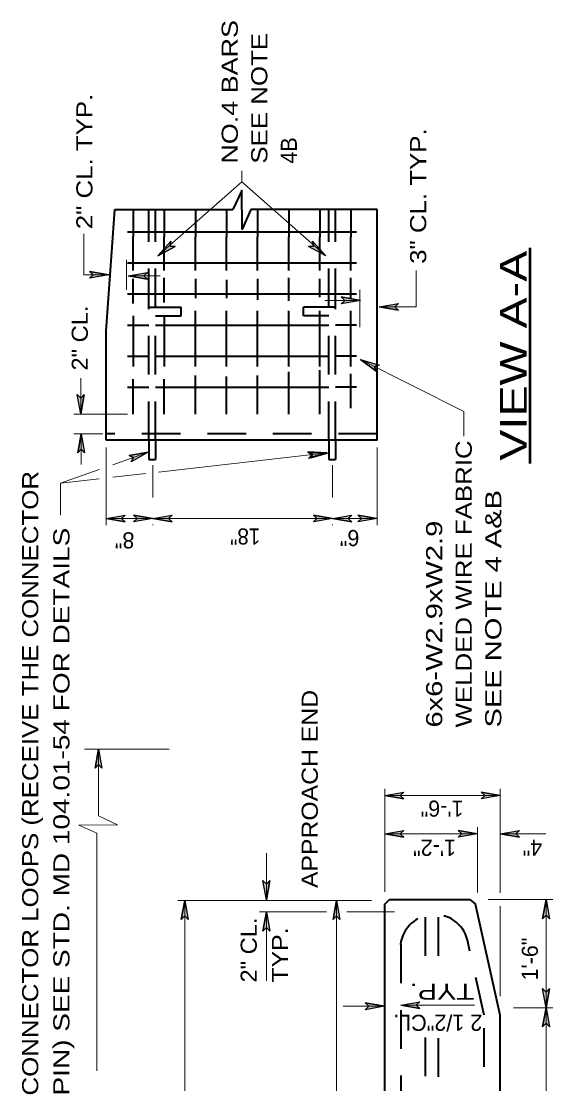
# Model space of a CAD drawing. Extents: x 12.6 to 19.5, y 6.1 to 16.3.
# Drawn here: x 12.689 to 14.668, y 12.348 to 16.307 of the extents above; entities that cross this region are included whole.
import ezdxf
from ezdxf.enums import TextEntityAlignment as Align

# ---------------------------------------------------------------- set-up
doc = ezdxf.new("R2010")
doc.units = 0
doc.header["$LTSCALE"] = 0.024
doc.linetypes.add('DOT_DASHED', pattern=[7.7, 5, -1.2, 0.3, -1.2])
doc.linetypes.add('LONG_DASHED', pattern=[7.5, 6, -1.5])
for name, color, linetype, lineweight in [('1', 7, 'Continuous', 35), ('10', 7, 'Continuous', 25), ('12', 7, 'Continuous', 53)]:
    doc.layers.add(name, color=color, linetype=linetype, lineweight=lineweight)

msp = doc.modelspace()

# ---------------------------------------------------------------- hatches: boundary and pattern name
at = {"layer": '10'}
for points in [[(13.2621, 15.4673), (13.1979, 15.4333), (13.2466, 15.4872), (13.2437, 15.4689)], [(13.7742, 15.4873), (13.8229, 15.4334), (13.7587, 15.4674), (13.7771, 15.469)], [(12.9436, 15.3746), (13.0151, 15.362), (12.9436, 15.3494), (12.9571, 15.362)], [(13.1589, 15.3461), (13.0874, 15.3587), (13.1589, 15.3713), (13.1454, 15.3587)], [(13.8805, 15.2797), (13.952, 15.2671), (13.8805, 15.2545), (13.894, 15.2671)], [(14.0935, 15.2305), (14.022, 15.2431), (14.0935, 15.2557), (14.08, 15.2431)], [(14.0104, 15.0033), (13.9522, 15.0466), (14.0217, 15.0258), (14.004, 15.0206)], [(12.9233, 14.9162), (12.9107, 14.8447), (12.8981, 14.9162), (12.9107, 14.9027)], [(12.8995, 14.6985), (12.9121, 14.77), (12.9247, 14.6985), (12.9121, 14.712)], [(13.0908, 14.689), (13.1624, 14.7008), (13.0991, 14.6652), (13.1077, 14.6816)], [(13.7563, 14.7029), (13.8288, 14.6984), (13.7592, 14.6778), (13.7712, 14.6919)], [(13.0765, 14.4418), (13.005, 14.4544), (13.0765, 14.467), (13.063, 14.4544)], [(13.1079, 14.467), (13.1794, 14.4544), (13.1079, 14.4418), (13.1214, 14.4544)], [(13.2509, 14.4418), (13.1794, 14.4544), (13.2509, 14.467), (13.2374, 14.4544)], [(13.777, 14.467), (13.8485, 14.4544), (13.777, 14.4418), (13.7905, 14.4544)], [(13.92, 14.4418), (13.8485, 14.4544), (13.92, 14.467), (13.9065, 14.4544)], [(13.9427, 14.467), (14.0142, 14.4544), (13.9427, 14.4418), (13.9562, 14.4544)], [(12.9644, 13.5238), (12.977, 13.5953), (12.9896, 13.5238), (12.977, 13.5373)], [(14.114, 13.4098), (14.0425, 13.4224), (14.114, 13.435), (14.1005, 13.4224)], [(14.4013, 13.435), (14.4728, 13.4224), (14.4013, 13.4098), (14.4148, 13.4224)], [(14.114, 13.2666), (14.0425, 13.2792), (14.114, 13.2918), (14.1005, 13.2792)], [(14.3161, 13.2918), (14.3876, 13.2792), (14.3161, 13.2666), (14.3296, 13.2792)], [(14.5443, 13.2664), (14.4728, 13.279), (14.5443, 13.2916), (14.5308, 13.279)], [(13.6145, 13.1051), (13.6019, 13.0336), (13.5893, 13.1051), (13.6019, 13.0916)], [(13.2852, 12.9596), (13.2978, 13.0311), (13.3104, 12.9596), (13.2978, 12.9731)], [(13.8509, 12.9596), (13.8635, 13.0311), (13.8761, 12.9596), (13.8635, 12.9731)], [(14.6306, 12.9627), (14.6432, 13.0342), (14.6558, 12.9627), (14.6432, 12.9762)], [(13.5893, 12.9169), (13.6019, 12.9884), (13.6145, 12.9169), (13.6019, 12.9304)], [(14.6558, 12.7028), (14.6432, 12.6313), (14.6306, 12.7028), (14.6432, 12.6893)], [(13.9699, 12.6492), (14.0414, 12.6366), (13.9699, 12.624), (13.9834, 12.6366)], [(14.1736, 12.6282), (14.1021, 12.6408), (14.1736, 12.6534), (14.1601, 12.6408)], [(14.6306, 12.5598), (14.6432, 12.6313), (14.6558, 12.5598), (14.6432, 12.5733)]]:
    msp.add_hatch(color=256, dxfattribs=at).paths.add_polyline_path(points)

# ---------------------------------------------------------------- linework, layer by layer
at = {"layer": '1'}
for p, q in [((13.0052, 15.1519), (13.0384, 15.6061)), ((13.0384, 15.6061), (13.4771, 15.6061)), ((13.1061, 15.6061), (13.1061, 15.5035)), ((13.2219, 15.6061), (13.2219, 15.5035)), ((13.3378, 15.6061), (13.3378, 15.5035)), ((13.4536, 15.6061), (13.4536, 15.5035)), ((14.0143, 15.6061), (13.5437, 15.6061)), ((13.5694, 15.6061), (13.5694, 15.5035)), ((13.6852, 15.6061), (13.6852, 15.5035)), ((13.8011, 15.6061), (13.8011, 15.5035)), ((13.9169, 15.6061), (13.9169, 15.5035)), ((14.0143, 14.7465), (14.0143, 15.6061)), ((13.0844, 15.5224), (13.9376, 15.5224)), ((13.1061, 15.3778), (13.1061, 15.5035)), ((13.2219, 15.3778), (13.2219, 15.5035)), ((13.3378, 15.3778), (13.3378, 15.5035)), ((13.4536, 15.3778), (13.4536, 15.5035)), ((13.5694, 15.3778), (13.5694, 15.5035)), ((13.6852, 15.3778), (13.6852, 15.5035)), ((13.8011, 15.3778), (13.8011, 15.5035)), ((13.9169, 15.3778), (13.9169, 15.5035)), ((13.0844, 15.4066), (13.9376, 15.4066)), ((13.1061, 15.2554), (13.1061, 15.3472)), ((13.2219, 15.2588), (13.2219, 15.3506)), ((13.3378, 15.3472), (13.3378, 15.2758)), ((13.4536, 15.3438), (13.4536, 15.2758)), ((13.5694, 15.3472), (13.5694, 15.2692)), ((13.6852, 15.2656), (13.6852, 15.3506)), ((13.8011, 15.2792), (13.8011, 15.3472)), ((13.9169, 15.2725), (13.9169, 15.3506)), ((13.0844, 15.2908), (13.9376, 15.2908)), ((13.1061, 15.2097), (13.1061, 15.021)), ((13.2219, 15.2097), (13.2219, 15.021)), ((13.0844, 15.175), (13.1643, 15.175)), ((13.1898, 15.175), (13.8342, 15.175)), ((13.9376, 15.175), (13.8597, 15.175)), ((13.0052, 14.7465), (13.0052, 15.1519)), ((13.0844, 15.0592), (13.1643, 15.0592)), ((13.1898, 15.0592), (13.8342, 15.0592)), ((13.9376, 15.0592), (13.8597, 15.0592)), ((13.8011, 14.8431), (13.8011, 15.0074)), ((13.1061, 14.8431), (13.1061, 14.9731)), ((13.2219, 14.8431), (13.2219, 14.9735)), ((13.3378, 14.8431), (13.3378, 14.9871)), ((13.4536, 14.8431), (13.4536, 14.9836)), ((13.5694, 14.8431), (13.5694, 14.9871)), ((13.6852, 14.8431), (13.6852, 15.0006)), ((13.9169, 14.8648), (13.9169, 14.9938)), ((13.0844, 14.9433), (13.1643, 14.9433)), ((13.1898, 14.9433), (13.8342, 14.9433)), ((13.9376, 14.9433), (13.8597, 14.9433)), ((14.0143, 14.7465), (13.0052, 14.7465)), ((13.1643, 14.7465), (13.1643, 14.6736)), ((13.1898, 14.7465), (13.1898, 14.6736)), ((13.8342, 14.7465), (13.8342, 14.6736)), ((13.8597, 14.7465), (13.8597, 14.6736)), ((13.7651, 14.7018), (13.8288, 14.6984)), ((13.7651, 14.7018), (13.7741, 14.6922)), ((13.7674, 14.6809), (13.8288, 14.6984)), ((13.7674, 14.6809), (13.7741, 14.6922)), ((13.1643, 14.6736), (13.1898, 14.6736)), ((13.8342, 14.6736), (13.8597, 14.6736)), ((14.0422, 13.0162), (14.0601, 13.0342)), ((14.0601, 13.0342), (14.3593, 13.0342)), ((14.3593, 13.0342), (14.3811, 13.0167)), ((14.4729, 12.6034), (14.3811, 13.0167))]:
    msp.add_line(p, q, dxfattribs=at)
at = {"layer": '1', "linetype": 'LONG_DASHED'}
for p, q in [((13.1643, 15.2414), (13.1643, 15.6061)), ((13.1898, 15.2414), (13.1898, 15.6061)), ((13.8342, 15.2414), (13.8342, 15.6061)), ((13.8597, 15.2414), (13.8597, 15.6061)), ((13.2843, 15.2097), (13.2843, 15.2414)), ((13.7397, 15.2097), (13.7397, 15.2414)), ((14.0143, 14.7702), (13.0052, 14.7702)), ((14.1928, 12.9684), (14.1928, 12.7394)), ((14.2415, 12.9684), (14.2415, 12.7394)), ((14.1021, 12.8664), (14.1021, 10.4224)), ((14.1928, 12.5199), (14.1928, 12.3566)), ((14.2415, 12.5182), (14.2415, 12.3548))]:
    msp.add_line(p, q, dxfattribs=at)
for points in [[(13.1643, 14.7465), (13.1643, 15.2414), (13.2843, 15.2414)], [(13.1898, 14.7465), (13.1898, 15.2097), (13.2843, 15.2097)], [(13.8597, 14.7465), (13.8597, 15.2414), (13.7397, 15.2414)], [(13.8342, 14.7465), (13.8342, 15.2097), (13.7397, 15.2097)], [(14.4131, 11.1916), (14.4131, 12.6034), (14.3534, 12.8719)]]:
    msp.add_lwpolyline(points, dxfattribs=at)
at = {"layer": '1'}
for points in [[(13.3378, 15.021), (13.3378, 15.1433), (13.3378, 15.2283)], [(13.4536, 15.021), (13.4536, 15.1433), (13.4536, 15.2283)], [(13.5694, 15.021), (13.5694, 15.1433), (13.5694, 15.2283)], [(13.6852, 15.021), (13.6852, 15.1433), (13.6852, 15.2283)], [(13.8011, 15.021), (13.8011, 15.1433), (13.8011, 15.2283)], [(13.9169, 15.021), (13.9169, 15.1433), (13.9169, 15.2283)], [(14.0422, 13.0162), (14.0422, 11.1916), (14.4729, 11.1916), (14.4729, 12.6034)]]:
    msp.add_lwpolyline(points, dxfattribs=at)
at = {"layer": '1', "linetype": 'LONG_DASHED'}
msp.add_arc((14.22776, 12.85181), 0.12725, 9.07504, 173.4317, dxfattribs=at)
at = {"layer": '10', "lineweight": 13}
for p, q in [((13.5104, 15.7092), (13.5104, 15.7503)), ((13.5104, 15.7092), (13.1979, 15.4333)), ((13.5104, 15.7092), (13.8229, 15.4333)), ((13.0808, 15.3058), (13.0808, 15.4182)), ((13.0874, 15.3587), (13.2063, 15.3587)), ((13.9496, 15.1672), (13.9496, 15.3059)), ((13.952, 15.2671), (13.82, 15.2671)), ((12.9107, 14.8447), (12.9107, 14.9767)), ((13.085, 14.8432), (12.8857, 14.8432)), ((12.9935, 14.77), (12.8857, 14.77)), ((12.9121, 14.77), (12.9121, 14.6551)), ((13.005, 14.7184), (13.005, 14.4294)), ((13.1624, 14.7008), (13.03, 14.6543)), ((13.8288, 14.6984), (13.1999, 14.6272)), ((14.0142, 14.4294), (14.0142, 14.7193)), ((12.835, 14.5858), (12.98, 14.6368)), ((13.03, 14.6079), (13.1526, 14.6218)), ((12.835, 14.5858), (12.98, 14.6021)), ((12.835, 14.4662), (12.835, 14.5858)), ((13.24, 13.5953), (12.9251, 13.5953)), ((12.977, 13.5953), (12.977, 13.3457)), ((14.0425, 13.0632), (14.0425, 13.4474)), ((14.4728, 13.4224), (14.0425, 13.4224)), ((14.4728, 13.4474), (14.4728, 13.0592)), ((14.3876, 13.0611), (14.3876, 13.3042)), ((12.9705, 12.3967), (12.9705, 13.2819)), ((14.3876, 13.2792), (14.0425, 13.2792)), ((14.4728, 13.279), (14.6429, 13.279)), ((13.6019, 13.0311), (13.6019, 13.2075)), ((13.5795, 13.0311), (13.2728, 13.0311)), ((13.2978, 8.7037), (13.2978, 13.0311)), ((13.9935, 13.0311), (13.5795, 13.0311)), ((14.4281, 13.0342), (14.6682, 13.0342)), ((13.5769, 12.9884), (13.8264, 12.9884)), ((13.6019, 12.9884), (13.6019, 12.7319)), ((14.0787, 12.9884), (13.9013, 12.9884)), ((14.4728, 12.6741), (14.4728, 13.0092)), ((14.0422, 12.6366), (13.8885, 12.6366)), ((14.1021, 12.6408), (14.377, 12.6408)), ((14.5218, 12.6313), (14.6682, 12.6313))]:
    msp.add_line(p, q, dxfattribs=at)
at = {"layer": '10'}
for p, q in [((13.1979, 15.4333), (13.2466, 15.4872)), ((13.8229, 15.4334), (13.7742, 15.4873)), ((13.1979, 15.4333), (13.2621, 15.4673)), ((13.8229, 15.4334), (13.7587, 15.4674)), ((13.0151, 15.362), (12.9436, 15.3746)), ((13.0151, 15.362), (12.9436, 15.3494)), ((13.0874, 15.3587), (13.1589, 15.3713)), ((13.0874, 15.3587), (13.1589, 15.3461)), ((13.952, 15.2671), (13.8805, 15.2797)), ((13.952, 15.2671), (13.8805, 15.2545)), ((14.022, 15.2431), (14.0935, 15.2557)), ((14.022, 15.2431), (14.0935, 15.2305)), ((13.9522, 15.0466), (14.0104, 15.0033)), ((13.9522, 15.0466), (14.0217, 15.0258)), ((12.9107, 14.8447), (12.8981, 14.9162)), ((12.9107, 14.8447), (12.9233, 14.9162)), ((12.9121, 14.77), (12.8995, 14.6985)), ((12.9121, 14.77), (12.9247, 14.6985)), ((13.1624, 14.7008), (13.0908, 14.689)), ((13.1624, 14.7008), (13.0991, 14.6652)), ((13.8288, 14.6984), (13.7563, 14.7029)), ((13.8288, 14.6984), (13.7592, 14.6778)), ((13.005, 14.4544), (13.0765, 14.467)), ((13.005, 14.4544), (13.0765, 14.4418)), ((13.1794, 14.4544), (13.1079, 14.467)), ((13.1794, 14.4544), (13.1079, 14.4418)), ((13.1794, 14.4544), (13.2509, 14.467)), ((13.1794, 14.4544), (13.2509, 14.4418)), ((13.8485, 14.4544), (13.777, 14.467)), ((13.8485, 14.4544), (13.777, 14.4418)), ((13.8485, 14.4544), (13.92, 14.467)), ((13.8485, 14.4544), (13.92, 14.4418)), ((14.0142, 14.4544), (13.9427, 14.467)), ((14.0142, 14.4544), (13.9427, 14.4418)), ((12.977, 13.5953), (12.9644, 13.5238)), ((12.977, 13.5953), (12.9896, 13.5238)), ((14.0425, 13.4224), (14.114, 13.435)), ((14.0425, 13.4224), (14.114, 13.4098)), ((14.4728, 13.4224), (14.4013, 13.435)), ((14.4728, 13.4224), (14.4013, 13.4098)), ((14.0425, 13.2792), (14.114, 13.2918)), ((14.0425, 13.2792), (14.114, 13.2666)), ((14.3876, 13.2792), (14.3161, 13.2918)), ((14.3876, 13.2792), (14.3161, 13.2666)), ((14.4728, 13.279), (14.5443, 13.2916)), ((14.4728, 13.279), (14.5443, 13.2664)), ((13.6019, 13.0336), (13.5893, 13.1051)), ((13.6019, 13.0336), (13.6145, 13.1051)), ((13.2978, 13.0311), (13.2852, 12.9596)), ((13.2978, 13.0311), (13.3104, 12.9596)), ((13.8635, 13.0311), (13.8509, 12.9596)), ((13.8635, 13.0311), (13.8761, 12.9596)), ((14.6432, 13.0342), (14.6306, 12.9627)), ((14.6432, 13.0342), (14.6558, 12.9627)), ((13.6019, 12.9884), (13.5893, 12.9169)), ((13.6019, 12.9884), (13.6145, 12.9169)), ((14.6432, 12.6313), (14.6306, 12.7028)), ((14.6432, 12.6313), (14.6558, 12.7028)), ((14.0414, 12.6366), (13.9699, 12.6492)), ((14.0414, 12.6366), (13.9699, 12.624)), ((14.1021, 12.6408), (14.1736, 12.6534)), ((14.1021, 12.6408), (14.1736, 12.6282)), ((14.6432, 12.6313), (14.6306, 12.5598)), ((14.6432, 12.6313), (14.6558, 12.5598))]:
    msp.add_line(p, q, dxfattribs=at)
at = {"layer": '10', "linetype": 'DOT_DASHED', "lineweight": 13}
for p, q in [((13.1794, 14.6524), (13.1794, 14.4294)), ((13.8485, 14.6524), (13.8485, 14.4294))]:
    msp.add_line(p, q, dxfattribs=at)
at = {"layer": '10', "lineweight": 35}
msp.add_lwpolyline([(13.5438, 15.6061), (13.5116, 15.5325), (13.5104, 15.6763), (13.4771, 15.6061)], dxfattribs=at)
at = {"layer": '10', "lineweight": 13}
for points in [[(13.0151, 15.362), (12.9228, 15.362), (12.9228, 15.5149)], [(14.022, 15.2431), (14.1602, 15.2431), (14.1602, 15.3787)], [(13.9522, 15.0466), (14.3378, 14.853), (14.3378, 14.761)], [(13.005, 14.4544), (13.1794, 14.4544), (13.8485, 14.4544), (14.0142, 14.4544)], [(12.9705, 13.2819), (12.9034, 13.3113), (13.0471, 13.3124), (12.977, 13.3457)], [(13.8635, 9.9472), (13.8635, 11.742), (13.8635, 13.0311)], [(14.6432, 11.1945), (14.6432, 12.6313), (14.6432, 13.0342)]]:
    msp.add_lwpolyline(points, dxfattribs=at)
at = {"layer": '10'}
for points in [[(13.2621, 15.4673), (13.1979, 15.4333), (13.2466, 15.4872), (13.2437, 15.4689)], [(13.7742, 15.4873), (13.8229, 15.4334), (13.7587, 15.4674), (13.7771, 15.469)], [(12.9436, 15.3746), (13.0151, 15.362), (12.9436, 15.3494), (12.9571, 15.362)], [(13.1589, 15.3461), (13.0874, 15.3587), (13.1589, 15.3713), (13.1454, 15.3587)], [(13.8805, 15.2797), (13.952, 15.2671), (13.8805, 15.2545), (13.894, 15.2671)], [(14.0935, 15.2305), (14.022, 15.2431), (14.0935, 15.2557), (14.08, 15.2431)], [(14.0104, 15.0033), (13.9522, 15.0466), (14.0217, 15.0258), (14.004, 15.0206)], [(12.9233, 14.9162), (12.9107, 14.8447), (12.8981, 14.9162), (12.9107, 14.9027)], [(12.8995, 14.6985), (12.9121, 14.77), (12.9247, 14.6985), (12.9121, 14.712)], [(13.0908, 14.689), (13.1624, 14.7008), (13.0991, 14.6652), (13.1077, 14.6816)], [(13.7563, 14.7029), (13.8288, 14.6984), (13.7592, 14.6778), (13.7712, 14.6919)], [(13.0765, 14.4418), (13.005, 14.4544), (13.0765, 14.467), (13.063, 14.4544)], [(13.1079, 14.467), (13.1794, 14.4544), (13.1079, 14.4418), (13.1214, 14.4544)], [(13.2509, 14.4418), (13.1794, 14.4544), (13.2509, 14.467), (13.2374, 14.4544)], [(13.777, 14.467), (13.8485, 14.4544), (13.777, 14.4418), (13.7905, 14.4544)], [(13.92, 14.4418), (13.8485, 14.4544), (13.92, 14.467), (13.9065, 14.4544)], [(13.9427, 14.467), (14.0142, 14.4544), (13.9427, 14.4418), (13.9562, 14.4544)], [(12.9644, 13.5238), (12.977, 13.5953), (12.9896, 13.5238), (12.977, 13.5373)], [(14.114, 13.4098), (14.0425, 13.4224), (14.114, 13.435), (14.1005, 13.4224)], [(14.4013, 13.435), (14.4728, 13.4224), (14.4013, 13.4098), (14.4148, 13.4224)], [(14.114, 13.2666), (14.0425, 13.2792), (14.114, 13.2918), (14.1005, 13.2792)], [(14.3161, 13.2918), (14.3876, 13.2792), (14.3161, 13.2666), (14.3296, 13.2792)], [(14.5443, 13.2664), (14.4728, 13.279), (14.5443, 13.2916), (14.5308, 13.279)], [(13.6145, 13.1051), (13.6019, 13.0336), (13.5893, 13.1051), (13.6019, 13.0916)], [(13.2852, 12.9596), (13.2978, 13.0311), (13.3104, 12.9596), (13.2978, 12.9731)], [(13.8509, 12.9596), (13.8635, 13.0311), (13.8761, 12.9596), (13.8635, 12.9731)], [(14.6306, 12.9627), (14.6432, 13.0342), (14.6558, 12.9627), (14.6432, 12.9762)], [(13.5893, 12.9169), (13.6019, 12.9884), (13.6145, 12.9169), (13.6019, 12.9304)], [(14.6558, 12.7028), (14.6432, 12.6313), (14.6306, 12.7028), (14.6432, 12.6893)], [(13.9699, 12.6492), (14.0414, 12.6366), (13.9699, 12.624), (13.9834, 12.6366)], [(14.1736, 12.6282), (14.1021, 12.6408), (14.1736, 12.6534), (14.1601, 12.6408)], [(14.6306, 12.5598), (14.6432, 12.6313), (14.6558, 12.5598), (14.6432, 12.5733)]]:
    msp.add_lwpolyline(points, close=True, dxfattribs=at)
for points in [[(13.2621, 15.4673), (13.2437, 15.4689), (13.2466, 15.4872)], [(13.7742, 15.4873), (13.7771, 15.469), (13.7587, 15.4674)], [(12.9436, 15.3746), (12.9571, 15.362), (12.9436, 15.3494)], [(13.1589, 15.3461), (13.1454, 15.3587), (13.1589, 15.3713)], [(13.8805, 15.2797), (13.894, 15.2671), (13.8805, 15.2545)], [(14.0935, 15.2305), (14.08, 15.2431), (14.0935, 15.2557)], [(14.0104, 15.0033), (14.004, 15.0206), (14.0217, 15.0258)], [(12.9233, 14.9162), (12.9107, 14.9027), (12.8981, 14.9162)], [(12.8995, 14.6985), (12.9121, 14.712), (12.9247, 14.6985)], [(13.0908, 14.689), (13.1077, 14.6816), (13.0991, 14.6652)], [(13.7563, 14.7029), (13.7712, 14.6919), (13.7592, 14.6778)], [(13.0765, 14.4418), (13.063, 14.4544), (13.0765, 14.467)], [(13.1079, 14.467), (13.1214, 14.4544), (13.1079, 14.4418)], [(13.2509, 14.4418), (13.2374, 14.4544), (13.2509, 14.467)], [(13.777, 14.467), (13.7905, 14.4544), (13.777, 14.4418)], [(13.92, 14.4418), (13.9065, 14.4544), (13.92, 14.467)], [(13.9427, 14.467), (13.9562, 14.4544), (13.9427, 14.4418)], [(12.9644, 13.5238), (12.977, 13.5373), (12.9896, 13.5238)], [(14.114, 13.4098), (14.1005, 13.4224), (14.114, 13.435)], [(14.4013, 13.435), (14.4148, 13.4224), (14.4013, 13.4098)], [(14.114, 13.2666), (14.1005, 13.2792), (14.114, 13.2918)], [(14.3161, 13.2918), (14.3296, 13.2792), (14.3161, 13.2666)], [(14.5443, 13.2664), (14.5308, 13.279), (14.5443, 13.2916)], [(13.6145, 13.1051), (13.6019, 13.0916), (13.5893, 13.1051)], [(13.2852, 12.9596), (13.2978, 12.9731), (13.3104, 12.9596)], [(13.8509, 12.9596), (13.8635, 12.9731), (13.8761, 12.9596)], [(14.6306, 12.9627), (14.6432, 12.9762), (14.6558, 12.9627)], [(13.5893, 12.9169), (13.6019, 12.9304), (13.6145, 12.9169)], [(14.6558, 12.7028), (14.6432, 12.6893), (14.6306, 12.7028)], [(13.9699, 12.6492), (13.9834, 12.6366), (13.9699, 12.624)], [(14.1736, 12.6282), (14.1601, 12.6408), (14.1736, 12.6534)], [(14.6306, 12.5598), (14.6432, 12.5733), (14.6558, 12.5598)]]:
    msp.add_lwpolyline(points, dxfattribs=at)
at = {"layer": '12'}
msp.add_line((14.5843, 14.6594), (14.5843, 15.4622), dxfattribs=at)

# ---------------------------------------------------------------- texts
for s, rotation, width, p in [('NO.4 BARS', 90, 1.25, (13.4956, 15.7766)), ('SEE NOTE', 90, 1.2, (13.6056, 15.7766)), ('2" CL. TYP.', 90, 1.2, (12.9544, 15.5321)), ('3" CL. TYP.', 90, 1.2, (14.197, 15.4031)), ('2" CL.', 90, 1.1, (12.9372, 15.0055)), ('WELDED WIRE FABRIC', 90, 1.2, (14.3668, 13.6755)), ('CONNECTOR LOOPS (RECEIVE THE CONNECTOR', 90, 1.2, (12.7526, 12.3042)), ('SEE NOTE 4 A&B', 90, 1.35, (14.4768, 13.6755)), ('PIN) SEE STD. MD 104.01-54 FOR DETAILS', 90, 1.3, (12.8688, 12.3042)), ('18"', 180, 0.95, (13.579, 14.4172)), ('6x6-W2.9xW2.9', 90, 1.35, (14.2568, 13.6755)), ('APPROACH END', 90, 1.15, (13.7935, 13.0772)), ('2" CL.', 90, 1.1, (13.5663, 12.7252)), ('TYP.', 90, 1.15, (13.6825, 12.7252)), (' TYP.', 180, 1.35, (14.406, 12.7213))]:
    msp.add_text(s, height=0.06, rotation=rotation, dxfattribs=dict(at, width=width)).set_placement(p)
for s, rotation, p in [('4B', 90, (13.7156, 15.7766)), ('6"', 180, (13.9484, 14.4114)), ('8"', 180, (13.1107, 14.4028)), ('1\'-6"', 180, (14.336, 13.4032)), ('1\'-2"', 180, (14.308, 13.2572)), ('4"', 180, (14.6293, 13.2574)), ('1\'-6"', 90, (14.6129, 12.7329)), ('2 1/2"CL.', 180, (14.406, 12.6052))]:
    msp.add_text(s, height=0.06, rotation=rotation, dxfattribs=at).set_placement(p)
at = {"layer": '12', "width": 1.3}
msp.add_text('VIEW A-A', height=0.1, rotation=90, dxfattribs=at).set_placement((14.5717, 15.0608), align=Align.CENTER)

doc.saveas('drawing.dxf')
